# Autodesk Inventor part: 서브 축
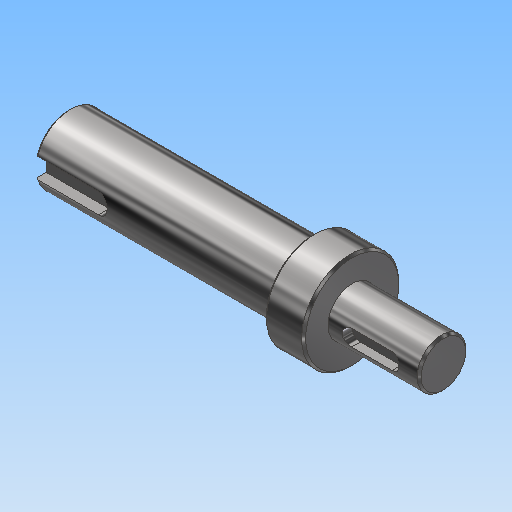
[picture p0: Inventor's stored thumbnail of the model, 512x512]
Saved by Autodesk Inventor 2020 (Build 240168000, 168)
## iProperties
Created: 2016-04
Part Number: 서브 축
Document SubType Name: Modeling
Designer: mdu
Density: 1 g/cm^3
Mass: 19.9624 g
Surface Area: 57.7178 cm^2
Volume: 19.9624 cm^3
Material: 강철, 연강
Appearance: 반광택
Author: mdu
Revision Number: 1
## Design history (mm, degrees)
sketch "스케치1"
  geometry: L1 (-16.331, 0)-(-108.831, 0); L2 (-16.331, 0)-(-16.331, -6); L3 (-16.331, -6)-(-38.831, -6); L4 (-38.831, -12)-(-46.5, -12); L5 (-46.5, -8.5)-(-108.831, -8.5); L6 (-108.831, -8.5)-(-108.831, 0); L7 (-46.5, -8.5)-(-46.5, -12); L8 (-38.831, -6)-(-38.831, -12); L9 (-46.5, 12.249)-(-46.5, -12.249) reference; L10 (-38.831, -17)-(-38.831, 17) reference; 2 further points
  constraints: 17 end point, 4 perpendicular, 2 collinear, 2 parallel, 1 horizontal, 1 midpoint, 1 point on line
  dimensions: "d1" = 12 diameter of L3 L1; "d2" = 24 diameter of L4 L1; "d3" = 17 diameter of L5 L1; "d18" = 22.5 distance of L2.end L3.end; "d20" = 70 distance between parallel lines of L6 L8; "d21" = 7.66872 distance of L4.start L4.end (derived)
revolve "회전1" sketch "스케치1" stored, may be unused: angle "d5" = 90 deg
feature "면 이동1"
chamfer "모따기1" distance "d6" = 0.5; stored, may be unused: second distance "d7" = 2, angle "d8" = 45 deg
node "작업 평면1"
sketch "스케치2"
  geometry: L1 (11.25, 5.5)-(11.25, -5.5) reference; L2 (-5.75, -2)-(4.25, -2); L3 (4.25, 2)-(-5.75, 2); A1 r 2 centre (4.25, 0) between (4.25, -2) and (4.25, 2); A2 r 2 centre (-5.75, 0) between (-5.75, 2) and (-5.75, -2); 2 further points
  constraints: 4 end point, 4 point on circle, 4 tangent, 2 centre point, 1 horizontal alignment, 1 midpoint, 1 parallel, 1 perpendicular
  dimensions: "d9" = 4 distance between parallel lines of L2 L3; "d10" = 14 dimension on A1 A2; "d11" = 5 distance edge to line of A1 L1
extrude "돌출1" cut sketch "스케치2" distance "d12" = 2.5; taper "d13" = 0 deg
node "작업 평면2"
sketch "스케치3"
  geometry: L1 (-31.166, -8)-(-31.166, 8) reference; L2 (-31.166, 2.5)-(-15.666, 2.5); L3 (-15.666, -2.5)-(-31.166, -2.5); A1 r 2.5 centre (-15.666, 0) between (-15.666, -2.5) and (-15.666, 2.5); 2 further points
  constraints: 4 end point, 2 perpendicular, 2 point on circle, 2 point on line, 2 tangent, 1 centre point, 1 horizontal alignment, 1 midpoint
  dimensions: "d14" = 5 distance between parallel lines of L3 L2; "d15" = 18 dimension on A1 L1
extrude "돌출2" cut sketch "스케치3" distance "d16" = 3; taper "d17" = 0 deg
node "솔리드1"
node "참조4"
node "참조5"
